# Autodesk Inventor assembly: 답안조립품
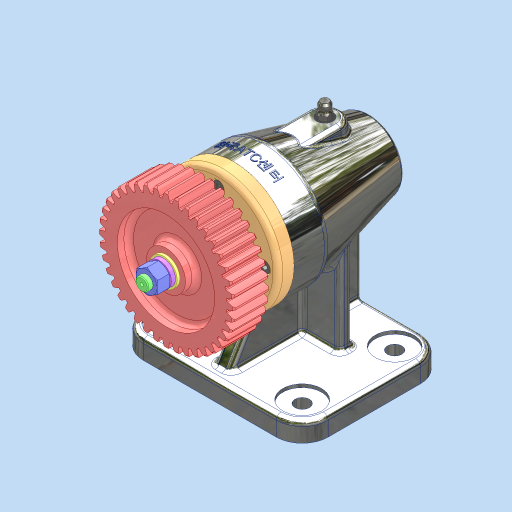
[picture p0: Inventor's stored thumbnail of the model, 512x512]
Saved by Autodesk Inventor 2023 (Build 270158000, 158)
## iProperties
Created: 2024-12
Part Number: 답안조립품
Document SubType Name: Assembly
Designer: asung
Author: asung
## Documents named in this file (15)
- C:\Users\asung\Desktop\741204V1015\답안조립품.iam
- C:\Users\asung\Desktop\741204V1015\본체.ipt
- C:\Users\asung\Desktop\741204V1015\앵귤러 볼 베어링 7003A.ipt
- C:\Users\asung\Desktop\741204V1015\축.ipt
- C:\Users\asung\Desktop\741204V1015\앵귤러 볼 제어링 7204A.ipt
- C:\Users\asung\Desktop\741204V1015\커버.ipt
- C:\Users\asung\Desktop\741204V1015\오일 실 20 32 8.ipt
- C:\Users\asung\Desktop\741204V1015\육각 소켓 머리 볼트 M4x10.ipt
- C:\Users\asung\Desktop\741204V1015\평행 키 4x4x14.ipt
- C:\Users\asung\Desktop\741204V1015\스퍼기어.ipt
- C:\Users\asung\Desktop\741204V1015\평와셔 M8.ipt
- C:\Users\asung\Desktop\741204V1015\스프링 와셔 M8.ipt
- C:\Users\asung\Desktop\741204V1015\육각 너트 M8.ipt
- C:\Users\asung\Desktop\741204V1015\실링.ipt
- C:\Users\asung\Desktop\741204V1015\그리스 니플 M6x0.75.ipt
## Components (1 placed, 1 different names)
1. 그리스 니플 M6x0.75:1
